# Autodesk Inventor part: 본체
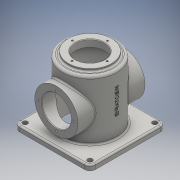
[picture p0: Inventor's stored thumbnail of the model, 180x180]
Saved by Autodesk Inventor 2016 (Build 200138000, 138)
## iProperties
Created: 2019-08
Part Number: 본체
Material: 일반
Document SubType Name: Modeling
Designer: user
Density: 1 g/cm^3
Appearance: 기본값
Author: user
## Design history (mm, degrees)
sketch "스케치1"
  geometry: C1 r 50 at (-0.332, 0); 1 further point
  constraints: 1 centre point
  dimensions: "d0" = 100 diameter of C1
extrude "돌출1" new body sketch "스케치1" distance "d1" = 110; taper "d2" = 0 deg
sketch "스케치2"
  geometry: 1 further point
sketch "스케치3"
  geometry: L1 (-70.332, -70)-(69.668, -70); L2 (69.668, -70)-(69.668, 70); L3 (69.668, 70)-(-70.332, 70); L4 (-70.332, 70)-(-70.332, -70); L5 (-70.332, -70)-(69.668, 70); L6 (69.668, -70)-(-70.332, 70); 1 further point
  constraints: 12 end point, 2 midpoint, 2 parallel, 1 horizontal, 1 perpendicular
  dimensions: "d3" = 140 distance of L3.end L2.end; "d4" = 140 distance of L2.end L1.end
extrude "돌출2" join sketch "스케치3" distance "d5" = 10; taper "d6" = 0 deg
sketch "스케치4"
  geometry: C1 r 45 at (-0.332, 0); 1 further point
  constraints: 1 centre point, 1 coincident
  dimensions: "d7" = 90 diameter of C1
extrude "돌출3" cut sketch "스케치4" distance "d8" = 112; taper "d9" = 0 deg
node "작업 평면1"
sketch "스케치5"
  geometry: L1 (70, -10)-(-70, -10) reference; L2 (50.332, 110)-(-49.668, 110) reference; L3 (0.332, 110)-(0, -10); C1 r 40 at (0.166, 50); 1 further point
  constraints: 2 end point, 2 midpoint, 1 centre point
  dimensions: "d11" = 80 diameter of C1; "d12" = 60 distance from line of C1.centre L1
extrude "돌출4" join sketch "스케치5" stored distance "d14" = 12; taper "d15" = 0 deg
sketch "스케치6" dims "d16" = 65
  geometry: C1 r 40 at (0, 0) reference; 3 further points
  constraints: 1 vertical alignment, 3 other
hole "구멍1" sketch "스케치6" at (0, -32.5) diameter "d17" = 3.242; stored, may be unused: countersink angle "d21" = 90 deg, drill point angle "d23" = 118 deg; dims "d18" = 8, "d19" = 4, "d20" = 2, "d22" = 10
sketch "스케치7"
  geometry: C1 r 27 at (0, 0); C2 r 40 at (0, 0) reference; 1 further point
  constraints: 1 centre point, 1 concentric
  dimensions: "d27" = 54 diameter of C1
extrude "돌출5" cut sketch "스케치7" distance "d28" = 62; taper "d29" = 0 deg
sketch "스케치8"
  geometry: C1 r 40 at (0.332, 0); 1 further point
  constraints: 1 centre point, 1 coincident
  dimensions: "d30" = 80 diameter of C1
extrude "돌출6" join sketch "스케치8" distance "d31" = 5; taper "d32" = 0 deg
sketch "스케치9" dims "d33" = 65
  geometry: 3 further points
  constraints: 1 coincident, 1 vertical alignment, 2 other
hole "구멍2" sketch "스케치9" at (0, 32.5) diameter "d34" = 3.242; stored, may be unused: countersink angle "d38" = 90 deg, drill point angle "d40" = 118 deg; dims "d35" = 8, "d36" = 4, "d37" = 2, "d39" = 10
sketch "스케치10"
  geometry: C1 r 27 at (0, 0); 1 further point
  constraints: 1 centre point, 1 coincident
  dimensions: "d44" = 54 diameter of C1
extrude "돌출7" cut sketch "스케치10" distance "d45" = 13; taper "d46" = 0 deg
fillet "모깎기1" dims "d47" = 10
hole "구멍3" diameter "d50" = 9; stored, may be unused: countersink angle "d54" = 90 deg, drill point angle "d56" = 0 deg; dims "d48" = 10, "d49" = 10, "d51" = 8, "d52" = 4, "d53" = 2, "d55" = 10
hole "구멍4" diameter "d59" = 9; stored, may be unused: countersink angle "d63" = 90 deg, drill point angle "d65" = 0 deg; dims "d57" = 10, "d58" = 10, "d60" = 8, "d61" = 4, "d62" = 2, "d64" = 10
hole "구멍5" diameter "d68" = 9; stored, may be unused: countersink angle "d72" = 90 deg, drill point angle "d74" = 0 deg; dims "d66" = 10, "d67" = 10, "d69" = 8, "d70" = 4, "d71" = 2, "d73" = 10
hole "구멍6" diameter "d77" = 9; stored, may be unused: countersink angle "d81" = 90 deg, drill point angle "d83" = 0 deg; dims "d75" = 10, "d76" = 10, "d78" = 8, "d79" = 4, "d80" = 2, "d82" = 10
fillet "모깎기2" dims "d84" = 3
fillet "모깎기3" dims "d85" = 5
chamfer "모따기1" distance "d86" = 1; stored, may be unused: second distance "d87" = 2, angle "d88" = 45 deg
chamfer "모따기2" distance "d89" = 1; stored, may be unused: second distance "d90" = 2, angle "d91" = 45 deg
chamfer "모따기3" distance "d92" = 1; stored, may be unused: second distance "d93" = 2, angle "d94" = 45 deg
node "작업 평면2"
sketch "스케치11"
  geometry: L1 (60, -10)-(-60, -10) reference; 2 further points
  constraints: 1 other
fillet "모깎기4" dims "d97" = 3
feature "엠보싱1" dims "d10" = 62, "d98" = 0.5, "d99" = 0
node "솔리드1"
pattern_circular "원형 패턴1" dims angle "d25" = 360 deg
mirror "대칭1"
pattern_circular "원형 패턴2" dims angle "d42" = 360 deg
